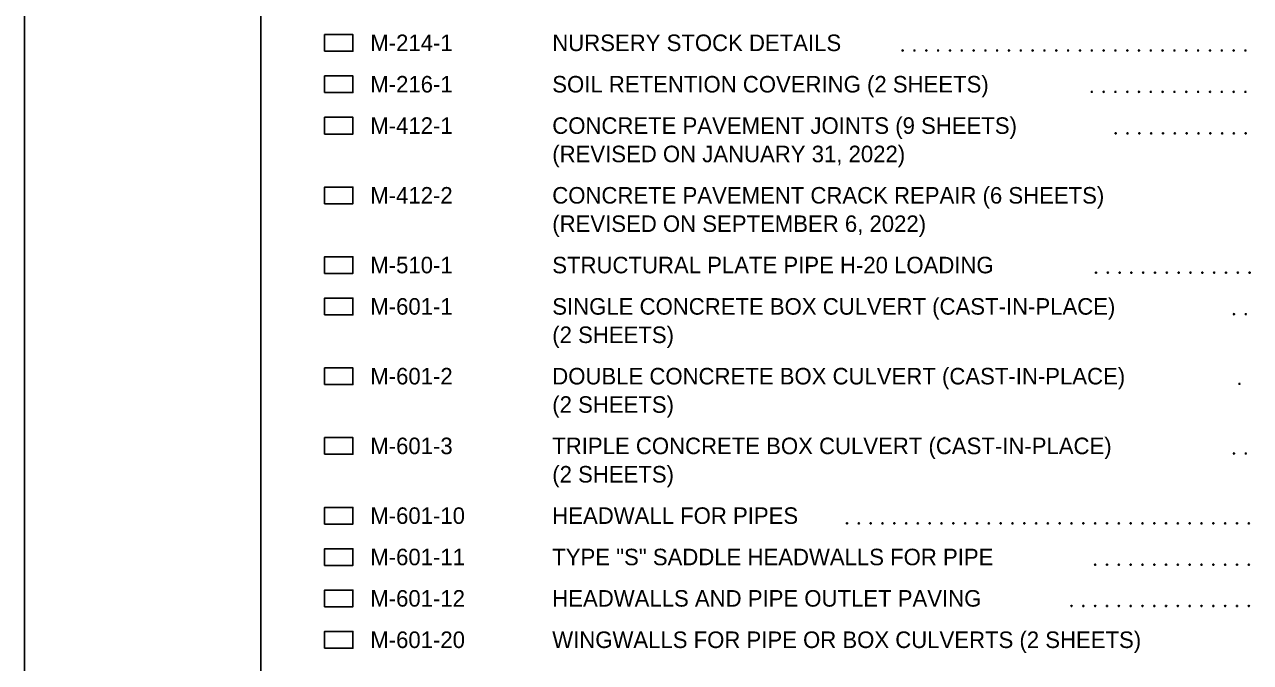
# Model space of a CAD drawing. Extents: x 0 to 1.42, y 0 to 0.92.
# Drawn here: x 0 to 0.4322, y 0.4595 to 0.6845 of the extents above; entities that cross this region are included whole.
import ezdxf

# ---------------------------------------------------------------- set-up
doc = ezdxf.new("R2010")
doc.units = 0
for name, color, linetype in [('DRAFT_Text-Notes', 7, 'Continuous'), ('DRAFT_Text-Titles', 7, 'Continuous'), ('SHEET_Lines', 7, 'Continuous'), ('SHEET_Plot Boundary', 7, 'Continuous')]:
    doc.layers.add(name, color=color, linetype=linetype)

msp = doc.modelspace()

# ---------------------------------------------------------------- linework, layer by layer
at = {"layer": 'DRAFT_Text-Notes'}
for centre in [(0.3096, 0.67536), (0.31377, 0.67536), (0.31793, 0.67536), (0.3221, 0.67536), (0.32627, 0.67536), (0.33043, 0.67536), (0.3346, 0.67536), (0.33877, 0.67536), (0.34293, 0.67536), (0.3471, 0.67536), (0.35127, 0.67536), (0.35543, 0.67536), (0.3596, 0.67536), (0.36377, 0.67536), (0.36793, 0.67536), (0.3721, 0.67536), (0.37627, 0.67536), (0.38043, 0.67536), (0.3846, 0.67536), (0.38877, 0.67536), (0.39293, 0.67536), (0.3971, 0.67536), (0.40127, 0.67536), (0.40543, 0.67536), (0.4096, 0.67536), (0.41377, 0.67536), (0.41793, 0.67536), (0.4221, 0.67536), (0.42627, 0.67536), (0.43043, 0.67536), (0.37627, 0.66077), (0.38043, 0.66077), (0.3846, 0.66077), (0.38877, 0.66077), (0.39293, 0.66077), (0.3971, 0.66077), (0.40127, 0.66077), (0.40543, 0.66077), (0.4096, 0.66077), (0.41377, 0.66077), (0.41793, 0.66077), (0.4221, 0.66077), (0.42627, 0.66077), (0.43043, 0.66077), (0.38471, 0.64618), (0.38887, 0.64618), (0.39304, 0.64618), (0.39721, 0.64618), (0.40137, 0.64618), (0.40554, 0.64618), (0.40971, 0.64618), (0.41387, 0.64618), (0.41804, 0.64618), (0.42221, 0.64618), (0.42637, 0.64618), (0.43054, 0.64618), (0.37773, 0.597), (0.3819, 0.597), (0.38607, 0.597), (0.39023, 0.597), (0.3944, 0.597), (0.39857, 0.597), (0.40273, 0.597), (0.4069, 0.597), (0.41107, 0.597), (0.41523, 0.597), (0.4194, 0.597), (0.42357, 0.597), (0.42773, 0.597), (0.4319, 0.597), (0.42641, 0.5824), (0.43057, 0.5824), (0.42837, 0.55781), (0.42641, 0.53322), (0.43057, 0.53322), (0.28996, 0.50863), (0.29413, 0.50863), (0.2983, 0.50863), (0.30246, 0.50863), (0.30663, 0.50863), (0.3108, 0.50863), (0.31496, 0.50863), (0.31913, 0.50863), (0.3233, 0.50863), (0.32746, 0.50863), (0.33163, 0.50863), (0.3358, 0.50863), (0.33996, 0.50863), (0.34413, 0.50863), (0.3483, 0.50863), (0.35246, 0.50863), (0.35663, 0.50863), (0.3608, 0.50863), (0.36496, 0.50863), (0.36913, 0.50863), (0.3733, 0.50863), (0.37746, 0.50863), (0.38163, 0.50863), (0.3858, 0.50863), (0.38996, 0.50863), (0.39413, 0.50863), (0.3983, 0.50863), (0.40246, 0.50863), (0.40663, 0.50863), (0.4108, 0.50863), (0.41496, 0.50863), (0.41913, 0.50863), (0.4233, 0.50863), (0.42746, 0.50863), (0.43163, 0.50863), (0.37746, 0.49404), (0.38163, 0.49404), (0.3858, 0.49404), (0.38996, 0.49404), (0.39413, 0.49404), (0.3983, 0.49404), (0.40246, 0.49404), (0.40663, 0.49404), (0.4108, 0.49404), (0.41496, 0.49404), (0.41913, 0.49404), (0.4233, 0.49404), (0.42746, 0.49404), (0.43163, 0.49404), (0.3733, 0.47944), (0.37746, 0.47944), (0.38163, 0.47944), (0.3858, 0.47944), (0.38996, 0.47944), (0.39413, 0.47944), (0.3983, 0.47944), (0.40246, 0.47944), (0.40663, 0.47944), (0.4108, 0.47944), (0.41496, 0.47944), (0.41913, 0.47944), (0.4233, 0.47944), (0.42746, 0.47944), (0.43163, 0.47944)]:
    msp.add_circle(centre, 0.000208, dxfattribs=at)
for centre, start, end in [((0.3096, 0.67536), 0, 180), ((0.3096, 0.67536), 180, 0), ((0.31377, 0.67536), 0, 180), ((0.31377, 0.67536), 180, 0), ((0.31793, 0.67536), 0, 180), ((0.31793, 0.67536), 180, 0), ((0.3221, 0.67536), 0, 180), ((0.3221, 0.67536), 180, 0), ((0.32627, 0.67536), 0, 180), ((0.32627, 0.67536), 180, 0), ((0.33043, 0.67536), 0, 180), ((0.33043, 0.67536), 180, 0), ((0.3346, 0.67536), 0, 180), ((0.3346, 0.67536), 180, 0), ((0.33877, 0.67536), 0, 180), ((0.33877, 0.67536), 180, 0), ((0.34293, 0.67536), 0, 180), ((0.34293, 0.67536), 180, 0), ((0.3471, 0.67536), 0, 180), ((0.3471, 0.67536), 180, 0), ((0.35127, 0.67536), 0, 180), ((0.35127, 0.67536), 180, 0), ((0.35543, 0.67536), 0, 180), ((0.35543, 0.67536), 180, 0), ((0.3596, 0.67536), 0, 180), ((0.3596, 0.67536), 180, 0), ((0.36377, 0.67536), 0, 180), ((0.36377, 0.67536), 180, 0), ((0.36793, 0.67536), 0, 180), ((0.36793, 0.67536), 180, 0), ((0.3721, 0.67536), 0, 180), ((0.3721, 0.67536), 180, 0), ((0.37627, 0.67536), 0, 180), ((0.37627, 0.67536), 180, 0), ((0.38043, 0.67536), 0, 180), ((0.38043, 0.67536), 180, 0), ((0.3846, 0.67536), 0, 180), ((0.3846, 0.67536), 180, 0), ((0.38877, 0.67536), 0, 180), ((0.38877, 0.67536), 180, 0), ((0.39293, 0.67536), 0, 180), ((0.39293, 0.67536), 180, 0), ((0.3971, 0.67536), 0, 180), ((0.3971, 0.67536), 180, 0), ((0.40127, 0.67536), 0, 180), ((0.40127, 0.67536), 180, 0), ((0.40543, 0.67536), 0, 180), ((0.40543, 0.67536), 180, 0), ((0.4096, 0.67536), 0, 180), ((0.4096, 0.67536), 180, 0), ((0.41377, 0.67536), 0, 180), ((0.41377, 0.67536), 180, 0), ((0.41793, 0.67536), 0, 180), ((0.41793, 0.67536), 180, 0), ((0.4221, 0.67536), 0, 180), ((0.4221, 0.67536), 180, 0), ((0.42627, 0.67536), 0, 180), ((0.42627, 0.67536), 180, 0), ((0.43043, 0.67536), 0, 180), ((0.43043, 0.67536), 180, 0), ((0.37627, 0.66077), 0, 180), ((0.37627, 0.66077), 180, 0), ((0.38043, 0.66077), 0, 180), ((0.38043, 0.66077), 180, 0), ((0.3846, 0.66077), 0, 180), ((0.3846, 0.66077), 180, 0), ((0.38877, 0.66077), 0, 180), ((0.38877, 0.66077), 180, 0), ((0.39293, 0.66077), 0, 180), ((0.39293, 0.66077), 180, 0), ((0.3971, 0.66077), 0, 180), ((0.3971, 0.66077), 180, 0), ((0.40127, 0.66077), 0, 180), ((0.40127, 0.66077), 180, 0), ((0.40543, 0.66077), 0, 180), ((0.40543, 0.66077), 180, 0), ((0.4096, 0.66077), 0, 180), ((0.4096, 0.66077), 180, 0), ((0.41377, 0.66077), 0, 180), ((0.41377, 0.66077), 180, 0), ((0.41793, 0.66077), 0, 180), ((0.41793, 0.66077), 180, 0), ((0.4221, 0.66077), 0, 180), ((0.4221, 0.66077), 180, 0), ((0.42627, 0.66077), 0, 180), ((0.42627, 0.66077), 180, 0), ((0.43043, 0.66077), 0, 180), ((0.43043, 0.66077), 180, 0), ((0.38471, 0.64618), 0, 180), ((0.38471, 0.64618), 180, 0), ((0.38887, 0.64618), 0, 180), ((0.38887, 0.64618), 180, 0), ((0.39304, 0.64618), 0, 180), ((0.39304, 0.64618), 180, 0), ((0.39721, 0.64618), 0, 180), ((0.39721, 0.64618), 180, 0), ((0.40137, 0.64618), 0, 180), ((0.40137, 0.64618), 180, 0), ((0.40554, 0.64618), 0, 180), ((0.40554, 0.64618), 180, 0), ((0.40971, 0.64618), 0, 180), ((0.40971, 0.64618), 180, 0), ((0.41387, 0.64618), 0, 180), ((0.41387, 0.64618), 180, 0), ((0.41804, 0.64618), 0, 180), ((0.41804, 0.64618), 180, 0), ((0.42221, 0.64618), 0, 180), ((0.42221, 0.64618), 180, 0), ((0.42637, 0.64618), 0, 180), ((0.42637, 0.64618), 180, 0), ((0.43054, 0.64618), 0, 180), ((0.43054, 0.64618), 180, 0), ((0.37773, 0.597), 0, 180), ((0.37773, 0.597), 180, 0), ((0.3819, 0.597), 0, 180), ((0.3819, 0.597), 180, 0), ((0.38607, 0.597), 0, 180), ((0.38607, 0.597), 180, 0), ((0.39023, 0.597), 0, 180), ((0.39023, 0.597), 180, 0), ((0.3944, 0.597), 0, 180), ((0.3944, 0.597), 180, 0), ((0.39857, 0.597), 0, 180), ((0.39857, 0.597), 180, 0), ((0.40273, 0.597), 0, 180), ((0.40273, 0.597), 180, 0), ((0.4069, 0.597), 0, 180), ((0.4069, 0.597), 180, 0), ((0.41107, 0.597), 0, 180), ((0.41107, 0.597), 180, 0), ((0.41523, 0.597), 0, 180), ((0.41523, 0.597), 180, 0), ((0.4194, 0.597), 0, 180), ((0.4194, 0.597), 180, 0), ((0.42357, 0.597), 0, 180), ((0.42357, 0.597), 180, 0), ((0.42773, 0.597), 0, 180), ((0.42773, 0.597), 180, 0), ((0.4319, 0.597), 0, 180), ((0.4319, 0.597), 180, 0), ((0.42641, 0.5824), 0, 180), ((0.42641, 0.5824), 180, 0), ((0.43057, 0.5824), 0, 180), ((0.43057, 0.5824), 180, 0), ((0.42837, 0.55781), 0, 180), ((0.42837, 0.55781), 180, 0), ((0.42641, 0.53322), 0, 180), ((0.42641, 0.53322), 180, 0), ((0.43057, 0.53322), 0, 180), ((0.43057, 0.53322), 180, 0), ((0.28996, 0.50863), 0, 180), ((0.28996, 0.50863), 180, 0), ((0.29413, 0.50863), 0, 180), ((0.29413, 0.50863), 180, 0), ((0.2983, 0.50863), 0, 180), ((0.2983, 0.50863), 180, 0), ((0.30246, 0.50863), 0, 180), ((0.30246, 0.50863), 180, 0), ((0.30663, 0.50863), 0, 180), ((0.30663, 0.50863), 180, 0), ((0.3108, 0.50863), 0, 180), ((0.3108, 0.50863), 180, 0), ((0.31496, 0.50863), 0, 180), ((0.31496, 0.50863), 180, 0), ((0.31913, 0.50863), 0, 180), ((0.31913, 0.50863), 180, 0), ((0.3233, 0.50863), 0, 180), ((0.3233, 0.50863), 180, 0), ((0.32746, 0.50863), 0, 180), ((0.32746, 0.50863), 180, 0), ((0.33163, 0.50863), 0, 180), ((0.33163, 0.50863), 180, 0), ((0.3358, 0.50863), 0, 180), ((0.3358, 0.50863), 180, 0), ((0.33996, 0.50863), 0, 180), ((0.33996, 0.50863), 180, 0), ((0.34413, 0.50863), 0, 180), ((0.34413, 0.50863), 180, 0), ((0.3483, 0.50863), 0, 180), ((0.3483, 0.50863), 180, 0), ((0.35246, 0.50863), 0, 180), ((0.35246, 0.50863), 180, 0), ((0.35663, 0.50863), 0, 180), ((0.35663, 0.50863), 180, 0), ((0.3608, 0.50863), 0, 180), ((0.3608, 0.50863), 180, 0), ((0.36496, 0.50863), 0, 180), ((0.36496, 0.50863), 180, 0), ((0.36913, 0.50863), 0, 180), ((0.36913, 0.50863), 180, 0), ((0.3733, 0.50863), 0, 180), ((0.3733, 0.50863), 180, 0), ((0.37746, 0.50863), 0, 180), ((0.37746, 0.50863), 180, 0), ((0.38163, 0.50863), 0, 180), ((0.38163, 0.50863), 180, 0), ((0.3858, 0.50863), 0, 180), ((0.3858, 0.50863), 180, 0), ((0.38996, 0.50863), 0, 180), ((0.38996, 0.50863), 180, 0), ((0.39413, 0.50863), 0, 180), ((0.39413, 0.50863), 180, 0), ((0.3983, 0.50863), 0, 180), ((0.3983, 0.50863), 180, 0), ((0.40246, 0.50863), 0, 180), ((0.40246, 0.50863), 180, 0), ((0.40663, 0.50863), 0, 180), ((0.40663, 0.50863), 180, 0), ((0.4108, 0.50863), 0, 180), ((0.4108, 0.50863), 180, 0), ((0.41496, 0.50863), 0, 180), ((0.41496, 0.50863), 180, 0), ((0.41913, 0.50863), 0, 180), ((0.41913, 0.50863), 180, 0), ((0.4233, 0.50863), 0, 180), ((0.4233, 0.50863), 180, 0), ((0.42746, 0.50863), 0, 180), ((0.42746, 0.50863), 180, 0), ((0.43163, 0.50863), 0, 180), ((0.43163, 0.50863), 180, 0), ((0.37746, 0.49404), 0, 180), ((0.37746, 0.49404), 180, 0), ((0.38163, 0.49404), 0, 180), ((0.38163, 0.49404), 180, 0), ((0.3858, 0.49404), 0, 180), ((0.3858, 0.49404), 180, 0), ((0.38996, 0.49404), 0, 180), ((0.38996, 0.49404), 180, 0), ((0.39413, 0.49404), 0, 180), ((0.39413, 0.49404), 180, 0), ((0.3983, 0.49404), 0, 180), ((0.3983, 0.49404), 180, 0), ((0.40246, 0.49404), 0, 180), ((0.40246, 0.49404), 180, 0), ((0.40663, 0.49404), 0, 180), ((0.40663, 0.49404), 180, 0), ((0.4108, 0.49404), 0, 180), ((0.4108, 0.49404), 180, 0), ((0.41496, 0.49404), 0, 180), ((0.41496, 0.49404), 180, 0), ((0.41913, 0.49404), 0, 180), ((0.41913, 0.49404), 180, 0), ((0.4233, 0.49404), 0, 180), ((0.4233, 0.49404), 180, 0), ((0.42746, 0.49404), 0, 180), ((0.42746, 0.49404), 180, 0), ((0.43163, 0.49404), 0, 180), ((0.43163, 0.49404), 180, 0), ((0.36913, 0.47944), 0, 180), ((0.36913, 0.47944), 180, 0), ((0.3733, 0.47944), 0, 180), ((0.3733, 0.47944), 180, 0), ((0.37746, 0.47944), 0, 180), ((0.37746, 0.47944), 180, 0), ((0.38163, 0.47944), 0, 180), ((0.38163, 0.47944), 180, 0), ((0.3858, 0.47944), 0, 180), ((0.3858, 0.47944), 180, 0), ((0.38996, 0.47944), 0, 180), ((0.38996, 0.47944), 180, 0), ((0.39413, 0.47944), 0, 180), ((0.39413, 0.47944), 180, 0), ((0.3983, 0.47944), 0, 180), ((0.3983, 0.47944), 180, 0), ((0.40246, 0.47944), 0, 180), ((0.40246, 0.47944), 180, 0), ((0.40663, 0.47944), 0, 180), ((0.40663, 0.47944), 180, 0), ((0.4108, 0.47944), 0, 180), ((0.4108, 0.47944), 180, 0), ((0.41496, 0.47944), 0, 180), ((0.41496, 0.47944), 180, 0), ((0.41913, 0.47944), 0, 180), ((0.41913, 0.47944), 180, 0), ((0.4233, 0.47944), 0, 180), ((0.4233, 0.47944), 180, 0), ((0.42746, 0.47944), 0, 180), ((0.42746, 0.47944), 180, 0), ((0.43163, 0.47944), 0, 180), ((0.43163, 0.47944), 180, 0)]:
    msp.add_arc(centre, 0.000208, start, end, dxfattribs=at)
at = {"layer": 'SHEET_Lines'}
msp.add_lwpolyline([(0.08333, 0.875), (1.375, 0.875), (1.375, 0.125), (0.08333, 0.125)], close=True, dxfattribs=at)
for points in [[(0.10578, 0.6751), (0.11575, 0.6751), (0.11575, 0.68099), (0.10578, 0.68099), (0.10578, 0.6751)], [(0.10578, 0.66051), (0.11575, 0.66051), (0.11575, 0.6664), (0.10578, 0.6664), (0.10578, 0.66051)], [(0.10578, 0.64592), (0.11575, 0.64592), (0.11575, 0.6518), (0.10578, 0.6518), (0.10578, 0.64592)], [(0.10578, 0.62133), (0.11575, 0.62133), (0.11575, 0.62721), (0.10578, 0.62721), (0.10578, 0.62133)], [(0.10578, 0.59673), (0.11575, 0.59673), (0.11575, 0.60262), (0.10578, 0.60262), (0.10578, 0.59673)], [(0.10578, 0.58214), (0.11575, 0.58214), (0.11575, 0.58803), (0.10578, 0.58803), (0.10578, 0.58214)], [(0.10578, 0.55755), (0.11575, 0.55755), (0.11575, 0.56344), (0.10578, 0.56344), (0.10578, 0.55755)], [(0.10578, 0.53296), (0.11575, 0.53296), (0.11575, 0.53884), (0.10578, 0.53884), (0.10578, 0.53296)], [(0.10578, 0.50837), (0.11575, 0.50837), (0.11575, 0.51425), (0.10578, 0.51425), (0.10578, 0.50837)], [(0.10578, 0.49377), (0.11575, 0.49377), (0.11575, 0.49966), (0.10578, 0.49966), (0.10578, 0.49377)], [(0.10578, 0.47918), (0.11575, 0.47918), (0.11575, 0.48507), (0.10578, 0.48507), (0.10578, 0.47918)], [(0.10578, 0.46459), (0.11575, 0.46459), (0.11575, 0.47048), (0.10578, 0.47048), (0.10578, 0.46459)]]:
    msp.add_lwpolyline(points, dxfattribs=at)
at = {"layer": 'SHEET_Plot Boundary'}
msp.add_lwpolyline([(0, 0.91667), (1.41667, 0.91667), (1.41667, 0), (0, 0)], close=True, dxfattribs=at)

# ---------------------------------------------------------------- texts
at = {"layer": 'DRAFT_Text-Notes'}
for s, height, p in [('M-214-1', 0.005833, (0.1219, 0.67516)), ('NURSERY STOCK DETAILS', 0.0058333, (0.18606, 0.67516)), ('M-216-1', 0.005833, (0.1219, 0.66056)), ('SOIL RETENTION COVERING (2 SHEETS)', 0.0058333, (0.18606, 0.66056)), ('M-412-1', 0.005833, (0.1219, 0.64597)), ('CONCRETE PAVEMENT JOINTS (9 SHEETS)', 0.0058333, (0.18606, 0.64597)), ('M-412-2', 0.005833, (0.1219, 0.62138)), ('CONCRETE PAVEMENT CRACK REPAIR (6 SHEETS)', 0.0058333, (0.18606, 0.62138)), ('M-510-1', 0.005833, (0.1219, 0.59679)), ('STRUCTURAL PLATE PIPE H-20 LOADING', 0.0058333, (0.18606, 0.59679)), ('M-601-1', 0.005833, (0.1219, 0.5822)), ('SINGLE CONCRETE BOX CULVERT (CAST-IN-PLACE)', 0.0058333, (0.18606, 0.5822)), ('(2 SHEETS)', 0.005833, (0.18606, 0.5722)), ('M-601-2', 0.005833, (0.1219, 0.5576)), ('DOUBLE CONCRETE BOX CULVERT (CAST-IN-PLACE)', 0.0058333, (0.18606, 0.5576)), ('(2 SHEETS)', 0.005833, (0.18606, 0.5476)), ('M-601-3', 0.005833, (0.1219, 0.53301)), ('TRIPLE CONCRETE BOX CULVERT (CAST-IN-PLACE)', 0.0058333, (0.18606, 0.53301)), ('(2 SHEETS)', 0.005833, (0.18606, 0.52301)), ('M-601-10', 0.005833, (0.1219, 0.50842)), ('HEADWALL FOR PIPES', 0.0058333, (0.18606, 0.50842)), ('M-601-11', 0.005833, (0.1219, 0.49383)), ('TYPE "S" SADDLE HEADWALLS FOR PIPE', 0.0058333, (0.18606, 0.49383)), ('M-601-12', 0.005833, (0.1219, 0.47924)), ('HEADWALLS AND PIPE OUTLET PAVING', 0.0058333, (0.18606, 0.47924)), ('M-601-20', 0.005833, (0.1219, 0.46464)), ('WINGWALLS FOR PIPE OR BOX CULVERTS (2 SHEETS)', 0.0058333, (0.18606, 0.46464))]:
    msp.add_text(s, height=height, dxfattribs=at).set_placement(p)
at = {"layer": 'DRAFT_Text-Titles'}
for s, p in [('(REVISED ON JANUARY 31, 2022)', (0.18606, 0.63597)), ('(REVISED ON SEPTEMBER 6, 2022)', (0.18606, 0.61138))]:
    msp.add_text(s, height=0.0058333, dxfattribs=at).set_placement(p)

doc.saveas('drawing.dxf')
